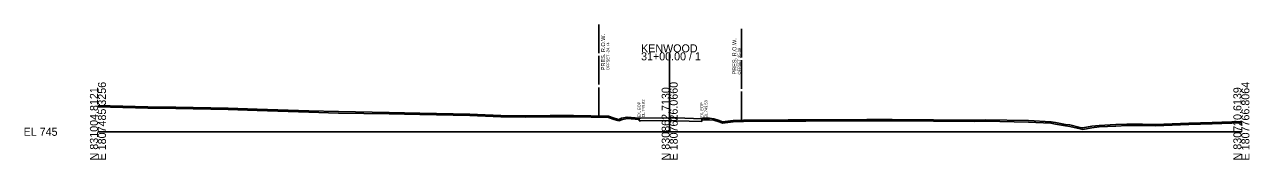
# Model space of a CAD drawing. Extents: x -293 to 1857107, y -10 to 831097.
# Drawn here: x -25.7 to 402.8, y -9.7 to 37.6 of the extents above; entities that cross this region are included whole.
import ezdxf

# ---------------------------------------------------------------- set-up
doc = ezdxf.new("R2010")
doc.units = 0
for name, color, linetype in [('DESIGN - SHEET - Light Grid', 7, 'Continuous'), ('SURVEY - GROUND - Bottom of Topsoil Layer', 7, 'Continuous'), ('SURVEY - GROUND - Existing Pavement Layer', 7, 'Continuous'), ('SURVEY - GROUND - Existing Pavement Text', 7, 'Continuous'), ('SURVEY - GROUND - Top of Ground', 7, 'Continuous'), ('SURVEY - PROPERTY - ROW Lines', 7, 'Continuous'), ('SURVEY - PROPERTY - ROW Lines Text', 7, 'Continuous')]:
    doc.layers.add(name, color=color, linetype=linetype)

msp = doc.modelspace()

# ---------------------------------------------------------------- linework, layer by layer
at = {"layer": 'DESIGN - SHEET - Light Grid'}
for p, q in [((200, 0), (200, 27.82)), ((0, 0), (200, 0)), ((200, 0), (400, 0))]:
    msp.add_line(p, q, dxfattribs=at)
at = {"layer": 'SURVEY - GROUND - Bottom of Topsoil Layer'}
for p, q in [((0, 8.77), (17.44, 8.25)), ((17.44, 8.25), (27.3, 8.15)), ((27.3, 8.15), (45.59, 7.82)), ((45.59, 7.82), (55.73, 7.46)), ((55.73, 7.46), (73.74, 6.83)), ((73.74, 6.83), (84.15, 6.58)), ((84.15, 6.58), (101.89, 6.25)), ((101.89, 6.25), (112.57, 6.07)), ((112.57, 6.07), (130.04, 5.68)), ((130.04, 5.68), (140.99, 5.23)), ((140.99, 5.23), (149.63, 5.15)), ((149.63, 5.15), (158.19, 5.19)), ((158.19, 5.19), (163.33, 5.25)), ((163.33, 5.25), (166.35, 5.26)), ((166.35, 5.26), (178.6, 5)), ((178.6, 5), (180.54, 4.28)), ((183.19, 4.24), (185.11, 4.66)), ((185.11, 4.66), (189.3, 4.32)), ((189.3, 4.32), (189.3, 4.82)), ((211.23, 4.59), (211.23, 4.09)), ((180.54, 4.28), (182.17, 3.84)), ((182.17, 3.84), (183.19, 4.24)), ((211.23, 4.09), (211.88, 4.25)), ((211.88, 4.25), (213.9, 4.24)), ((213.9, 4.24), (215.47, 4.07)), ((215.47, 4.07), (217.35, 3.48)), ((217.35, 3.48), (218.53, 3.04)), ((218.53, 3.04), (221.26, 3.34)), ((221.26, 3.34), (222.21, 3.46)), ((222.21, 3.46), (225.87, 3.6)), ((225.87, 3.6), (241.48, 3.74)), ((241.48, 3.74), (247.65, 3.73)), ((247.65, 3.73), (268.98, 3.85)), ((268.98, 3.85), (277.88, 3.84)), ((277.88, 3.84), (306.74, 3.63)), ((306.74, 3.63), (310.46, 3.72)), ((310.46, 3.72), (325.54, 3.43)), ((325.54, 3.43), (333.38, 3.05)), ((333.38, 3.05), (335.02, 2.73)), ((335.02, 2.73), (338.47, 2.1)), ((338.47, 2.1), (339.98, 1.91)), ((339.98, 1.91), (343.63, 1.04)), ((343.63, 1.04), (344.48, 0.84)), ((344.48, 0.84), (347.74, 1.44)), ((347.74, 1.44), (350.25, 1.76)), ((350.25, 1.76), (356.1, 2.02)), ((356.1, 2.02), (359.96, 2.21)), ((359.96, 2.21), (365.36, 2.23)), ((365.36, 2.23), (369.99, 2.12)), ((369.99, 2.12), (381.58, 2.56)), ((381.58, 2.56), (389.76, 2.81)), ((389.76, 2.81), (400, 3.12))]:
    msp.add_line(p, q, dxfattribs=at)
at = {"layer": 'SURVEY - GROUND - Existing Pavement Layer'}
for p, q in [((189.3, 3.82), (189.3, 4.82)), ((211.23, 4.59), (211.23, 3.59)), ((189.3, 3.82), (189.77, 3.82)), ((189.77, 3.82), (200.21, 3.92)), ((200.21, 3.92), (202.39, 3.86)), ((202.39, 3.86), (211.23, 3.59))]:
    msp.add_line(p, q, dxfattribs=at)
at = {"layer": 'SURVEY - GROUND - Top of Ground'}
msp.add_lwpolyline([(0, 9.27), (17.44, 8.75), (27.3, 8.65), (45.59, 8.32), (55.73, 7.96), (73.74, 7.33), (84.15, 7.08), (101.89, 6.75), (112.57, 6.57), (130.04, 6.18), (140.99, 5.73), (149.63, 5.65), (158.19, 5.69), (163.33, 5.75), (166.35, 5.76), (178.6, 5.5), (180.54, 4.78), (182.17, 4.34), (183.19, 4.74), (185.11, 5.16), (189.3, 4.82), (189.77, 4.82), (200.21, 4.92), (202.39, 4.86), (211.23, 4.59), (211.88, 4.75), (213.9, 4.74), (215.47, 4.57), (217.35, 3.98), (218.53, 3.54), (221.26, 3.84), (222.21, 3.96), (225.87, 4.1), (241.48, 4.24), (247.65, 4.23), (268.98, 4.35), (277.88, 4.34), (306.74, 4.13), (310.46, 4.22), (325.54, 3.93), (333.38, 3.55), (335.02, 3.23), (338.47, 2.6), (339.98, 2.41), (343.63, 1.54), (344.48, 1.34), (347.74, 1.94), (350.25, 2.26), (356.1, 2.52), (359.96, 2.71), (365.36, 2.73), (369.99, 2.62), (381.58, 3.06), (389.76, 3.31), (400, 3.62)], dxfattribs=at)
at = {"layer": 'SURVEY - PROPERTY - ROW Lines'}
for p, q in [((175.26, 27.57), (175.26, 37.57)), ((225.09, 26.07), (225.09, 36.07)), ((175.26, 16.57), (175.26, 26.57)), ((225.09, 15.07), (225.09, 25.07)), ((175.26, 5.57), (175.26, 15.57)), ((225.09, 4.07), (225.09, 14.07))]:
    msp.add_line(p, q, dxfattribs=at)

# ---------------------------------------------------------------- texts
at = {"layer": 'DESIGN - SHEET - Light Grid'}
for s, p in [('KENWOOD', (190, 27.82)), ('31+00.00 / 1', (190, 25.02)), ('EL 745', (-26, -1.4))]:
    msp.add_text(s, height=2.8, dxfattribs=at).set_placement(p)
for s, p in [('E 1807485.3256', (2.8, -10)), ('E 1807626.0660', (202.8, -10)), ('E 1807766.8064', (402.8, -10)), ('N 831004.8121', (0, -10)), ('N 830862.7130', (200, -10)), ('N 830720.6139', (400, -10))]:
    msp.add_text(s, height=2.8, rotation=90, dxfattribs=at).set_placement(p)
at = {"layer": 'SURVEY - GROUND - Existing Pavement Text'}
for s, p in [('EX. EOP', (189.8, 5.02)), ('EL.749.82', (191.3, 5.02)), ('EX. EOP', (211.73, 4.79)), ('EL.749.59', (213.23, 4.79))]:
    msp.add_text(s, height=1, rotation=90, dxfattribs=at).set_placement(p)
at = {"layer": 'SURVEY - PROPERTY - ROW Lines Text'}
for s, height, p in [('PRES. R.O.W.', 1.4, (177.41, 21.57)), ('OFFSET -24.74', 1, (178.91, 21.57)), ('PRES. R.O.W.', 1.4, (223.34, 20.07)), ('OFFSET 25.09', 1, (224.84, 20.07))]:
    msp.add_text(s, height=height, rotation=90, dxfattribs=at).set_placement(p)

doc.saveas('drawing.dxf')
